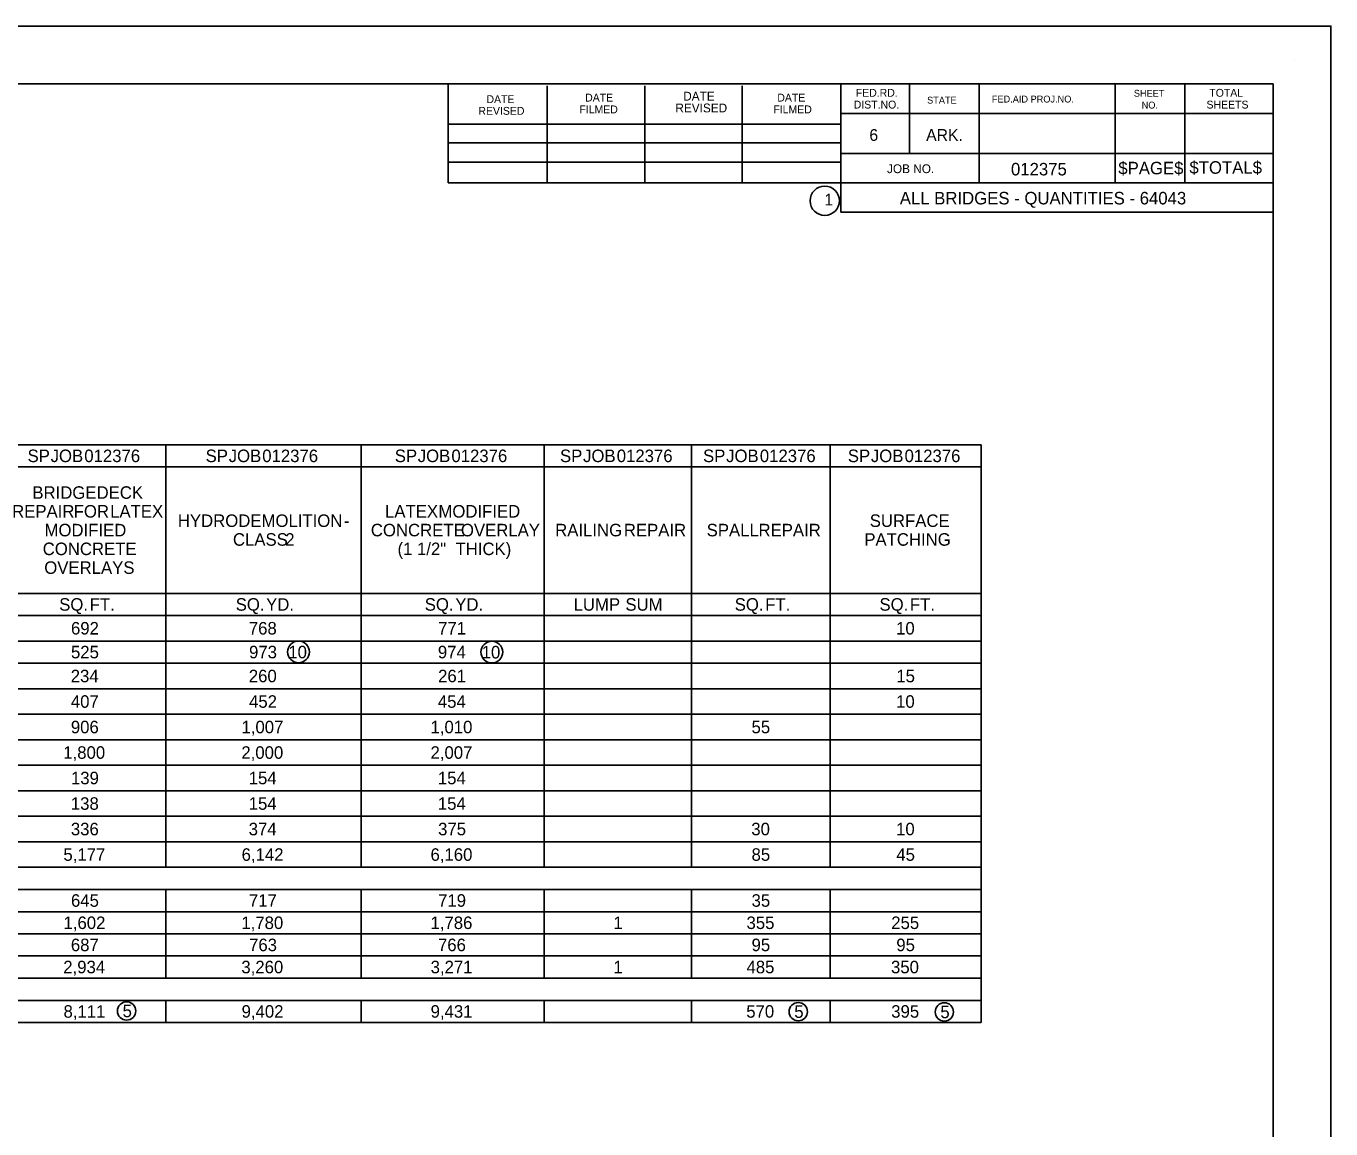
# Model space of a CAD drawing. Extents: x 16 to 1228740, y 11 to 152440.
# Drawn here: x 17.406 to 18.49, y 11.626 to 12.543 of the extents above; entities that cross this region are included whole.
import ezdxf

# ---------------------------------------------------------------- set-up
doc = ezdxf.new("R2010")
doc.units = 0
for name, color, linetype in [('B_Copy In', 7, 'Continuous'), ('B_Text', 7, 'Continuous'), ('Default', 7, 'Continuous'), ('R_Border', 7, 'Continuous')]:
    doc.layers.add(name, color=color, linetype=linetype)

msp = doc.modelspace()

# ---------------------------------------------------------------- linework, layer by layer
at = {"layer": 'B_Text'}
for centre, radius in [((17.6323, 12.0226), 0.00906), ((17.793, 12.0225), 0.00906), ((17.4894, 11.7242), 0.00762), ((18.0476, 11.7236), 0.00762), ((18.169, 11.7234), 0.00762)]:
    msp.add_circle(centre, radius, dxfattribs=at)
at = {"layer": 'Default'}
for p, q in [((16.0259, 12.1948), (18.1996, 12.1948)), ((17.522, 11.8436), (17.522, 12.1948)), ((17.6843, 11.8436), (17.6843, 12.1948)), ((17.8364, 11.8436), (17.8364, 12.1948)), ((17.959, 11.8436), (17.959, 12.1948)), ((18.0742, 11.8436), (18.0742, 12.1948)), ((18.1996, 11.7146), (18.1996, 12.1948)), ((16.7459, 12.1764), (18.1996, 12.1764)), ((16.7459, 12.0713), (18.1996, 12.0713)), ((16.0259, 12.0529), (18.1996, 12.0529)), ((16.1015, 12.0317), (18.1996, 12.0317)), ((16.1015, 12.0132), (18.1996, 12.0132)), ((16.1015, 11.992), (18.1996, 11.992)), ((16.1015, 11.9708), (18.1996, 11.9708)), ((16.1015, 11.9496), (18.1996, 11.9496)), ((16.1015, 11.9284), (18.1996, 11.9284)), ((16.1015, 11.9072), (18.1996, 11.9072)), ((16.1015, 11.886), (18.1996, 11.886)), ((16.1015, 11.8648), (18.1996, 11.8648)), ((16.0259, 11.8436), (18.1996, 11.8436)), ((16.0259, 11.8252), (18.1996, 11.8252)), ((17.522, 11.7514), (17.522, 11.8252)), ((17.6843, 11.7514), (17.6843, 11.8252)), ((17.8364, 11.7514), (17.8364, 11.8252)), ((17.959, 11.7514), (17.959, 11.8252)), ((18.0742, 11.7514), (18.0742, 11.8252)), ((16.1015, 11.8067), (18.1996, 11.8067)), ((16.1015, 11.7883), (18.1996, 11.7883)), ((16.1015, 11.7699), (18.1996, 11.7699)), ((16.0259, 11.7514), (18.1996, 11.7514)), ((16.0259, 11.733), (18.1996, 11.733)), ((17.522, 11.7146), (17.522, 11.733)), ((17.6843, 11.7146), (17.6843, 11.733)), ((17.8364, 11.7146), (17.8364, 11.733)), ((17.959, 11.7146), (17.959, 11.733)), ((18.0742, 11.7146), (18.0742, 11.733)), ((16.0259, 11.7146), (18.1996, 11.7146))]:
    msp.add_line(p, q, dxfattribs=at)
at = {"layer": 'R_Border'}
for p, q in [((18.4604, 12.514), (18.4604, 12.514)), ((15.7833, 12.4948), (18.4422, 12.4948)), ((17.7567, 12.4124), (17.7567, 12.4948)), ((17.8389, 12.4124), (17.8389, 12.4931)), ((17.9202, 12.4124), (17.9202, 12.4931)), ((18.0009, 12.4124), (18.0009, 12.4931)), ((18.083, 12.4948), (18.083, 12.3881)), ((18.14, 12.4948), (18.14, 12.4369)), ((18.1979, 12.4948), (18.1979, 12.4124)), ((18.311, 12.4948), (18.311, 12.4124)), ((18.3689, 12.4948), (18.3689, 12.4124)), ((18.4422, 10.7576), (18.4422, 12.4948)), ((18.4422, 12.4704), (18.4422, 12.4704)), ((17.7567, 12.4613), (18.083, 12.4613)), ((18.4422, 12.4703), (18.083, 12.4703)), ((17.7567, 12.4458), (18.083, 12.4458)), ((17.7567, 12.4124), (17.7567, 12.4296)), ((17.7567, 12.4296), (18.083, 12.4296)), ((18.4422, 12.4369), (18.083, 12.4369)), ((18.1077, 12.4369), (18.4422, 12.4369)), ((18.4422, 12.4124), (17.7567, 12.4124)), ((18.083, 12.3881), (18.4422, 12.3881)), ((18.083, 12.3881), (18.4422, 12.3881))]:
    msp.add_line(p, q, dxfattribs=at)
msp.add_lwpolyline([(15.6569, 12.5428), (18.4903, 12.5428), (18.4903, 10.7095), (15.6569, 10.7095)], close=True, dxfattribs=at)
msp.add_circle((18.0696, 12.3976), 0.0122, dxfattribs=at)

# ---------------------------------------------------------------- texts
at = {"layer": 'B_Copy In'}
msp.add_text('ALL BRIDGES - QUANTITIES - 64043', height=0.0104, dxfattribs=at).set_placement((18.132, 12.3946))
at = {"layer": 'B_Text'}
for s, height, p in [('10', 0.01042, (17.6238, 12.0173)), ('10', 0.01042, (17.7845, 12.0172)), ('5', 0.0104, (17.4861, 11.719)), ('5', 0.0104, (18.0443, 11.7184)), ('5', 0.0104, (18.1657, 11.7182))]:
    msp.add_text(s, height=height, dxfattribs=at).set_placement(p)
at = {"layer": 'Default'}
for s, p in [('SP', (17.4071, 12.1804)), (' JOB', (17.4224, 12.1804)), (' 012376', (17.4504, 12.1804)), ('SP', (17.5551, 12.1804)), (' JOB', (17.5704, 12.1804)), (' 012376', (17.5983, 12.1804)), ('SP', (17.7123, 12.1804)), (' JOB', (17.7275, 12.1804)), (' 012376', (17.7555, 12.1804)), ('SP', (17.8496, 12.1804)), (' JOB', (17.8649, 12.1804)), (' 012376', (17.8929, 12.1804)), ('SP', (17.9685, 12.1804)), (' JOB', (17.9838, 12.1804)), (' 012376', (18.0118, 12.1804)), ('SP', (18.0888, 12.1804)), (' JOB', (18.1041, 12.1804)), (' 012376', (18.1321, 12.1804)), ('BRIDGE', (17.4111, 12.1499)), (' DECK', (17.4606, 12.1499)), ('REPAIR', (17.3943, 12.1343)), (' FOR', (17.4416, 12.1343)), (' LATEX', (17.4719, 12.1343)), ('HYDRODEMOLITION', (17.532, 12.1265)), ('LATEX', (17.7042, 12.1343)), (' MODIFIED', (17.7447, 12.1343)), ('SURFACE', (18.107, 12.1265)), ('MODIFIED', (17.4212, 12.1187)), (' -', (17.6661, 12.1265)), ('CONCRETE', (17.6924, 12.1187)), (' OVERLAY', (17.7634, 12.1187)), ('RAILING', (17.8456, 12.1187)), (' REPAIR', (17.8988, 12.1187)), ('SPALL', (17.9715, 12.1187)), (' REPAIR', (18.0107, 12.1187)), ('CONCRETE', (17.4197, 12.1031)), ('CLASS', (17.5778, 12.1109)), (' 2', (17.6174, 12.1109)), ('(1', (17.7146, 12.1031)), (' 1/2"', (17.7269, 12.1031)), (' THICK)', (17.7589, 12.1031)), ('PATCHING', (18.1025, 12.1109)), ('OVERLAYS', (17.421, 12.0875)), ('SQ.', (17.4334, 12.0569)), (' FT.', (17.4549, 12.0569)), ('SQ.', (17.5801, 12.0569)), (' YD.', (17.6015, 12.0569)), ('SQ.', (17.7372, 12.0569)), (' YD.', (17.7587, 12.0569)), ('LUMP', (17.8609, 12.0569)), (' SUM', (17.9001, 12.0569)), ('SQ.', (17.9948, 12.0569)), (' FT.', (18.0163, 12.0569)), ('SQ.', (18.1151, 12.0569)), (' FT.', (18.1365, 12.0569)), ('692', (17.4432, 12.0371)), ('768', (17.591, 12.0371)), ('771', (17.7483, 12.0371)), ('10', (18.1289, 12.0371)), ('525', (17.4432, 12.0173)), ('973', (17.5912, 12.0173)), ('974', (17.7481, 12.0173)), ('234', (17.443, 11.9974)), ('260', (17.591, 11.9974)), ('261', (17.7483, 11.9974)), ('15', (18.1291, 11.9974)), ('407', (17.4431, 11.9762)), ('452', (17.5912, 11.9762)), ('454', (17.7481, 11.9762)), ('10', (18.1289, 11.9762)), ('906', (17.4431, 11.955)), ('1,007', (17.5849, 11.955)), ('1,010', (17.742, 11.955)), ('55', (18.0088, 11.955)), ('1,800', (17.4368, 11.9338)), ('2,000', (17.5848, 11.9338)), ('2,007', (17.742, 11.9338)), ('139', (17.4432, 11.9126)), ('154', (17.5909, 11.9126)), ('154', (17.7481, 11.9126)), ('138', (17.4431, 11.8914)), ('154', (17.5909, 11.8914)), ('154', (17.7481, 11.8914)), ('336', (17.4431, 11.8702)), ('374', (17.5909, 11.8702)), ('375', (17.7483, 11.8702)), ('30', (18.0086, 11.8702)), ('10', (18.1289, 11.8702)), ('5,177', (17.4369, 11.849)), ('6,142', (17.585, 11.849)), ('6,160', (17.742, 11.849)), ('85', (18.0088, 11.849)), ('45', (18.1291, 11.849)), ('645', (17.4432, 11.8108)), ('717', (17.5911, 11.8108)), ('719', (17.7483, 11.8108)), ('35', (18.0088, 11.8108)), ('1,602', (17.437, 11.7923)), ('1,780', (17.5848, 11.7923)), ('1,786', (17.742, 11.7923)), ('1', (17.894, 11.7923)), ('355', (18.0046, 11.7923)), ('255', (18.1249, 11.7923)), ('687', (17.4431, 11.7739)), ('763', (17.5912, 11.7739)), ('766', (17.7482, 11.7739)), ('95', (18.0088, 11.7739)), ('95', (18.1291, 11.7739)), ('2,934', (17.4368, 11.7555)), ('3,260', (17.5848, 11.7555)), ('3,271', (17.7421, 11.7555)), ('1', (17.894, 11.7555)), ('485', (18.0046, 11.7555)), ('350', (18.1247, 11.7555)), ('8,111', (17.437, 11.7186)), ('9,402', (17.585, 11.7186)), ('9,431', (17.7421, 11.7186)), ('570', (18.0044, 11.7186)), ('395', (18.1249, 11.7186))]:
    msp.add_text(s, height=0.0104, dxfattribs=at).set_placement(p)
at = {"layer": 'R_Border'}
for s, height, p in [('DATE', 0.00652, (17.7885, 12.4788)), ('DATE', 0.00652, (17.8705, 12.4801)), ('DATE', 0.00733, (17.952, 12.4809)), ('DATE', 0.00652, (18.0302, 12.4801)), ('FED.RD.', 0.00652, (18.0954, 12.4841)), ('STATE', 0.0057, (18.1547, 12.4784)), ('FED.AID PROJ.NO.', 0.0057, (18.2085, 12.4793)), ('SHEET', 0.0057, (18.3265, 12.4841)), ('TOTAL', 0.00652, (18.3892, 12.4841)), ('REVISED', 0.00652, (17.7818, 12.4691)), ('FILMED', 0.00652, (17.8657, 12.4703)), ('REVISED', 0.00733, (17.9455, 12.4711)), ('FILMED', 0.00652, (18.0269, 12.4703)), ('DIST.NO.', 0.00652, (18.0937, 12.4743)), ('NO.', 0.0057, (18.333, 12.4743)), ('SHEETS', 0.00652, (18.3869, 12.4743)), ('6', 0.00977, (18.1067, 12.4474)), ('ARK.', 0.00977, (18.1539, 12.4474)), ('JOB NO.', 0.00733, (18.1214, 12.4206)), ('012375', 0.0104, (18.2244, 12.4187)), ('$PAGE$', 0.0104, (18.3136, 12.4196)), ('$TOTAL$', 0.0104, (18.3727, 12.4201)), ('1', 0.00977, (18.0693, 12.3937))]:
    msp.add_text(s, height=height, dxfattribs=at).set_placement(p)

doc.saveas('drawing.dxf')
